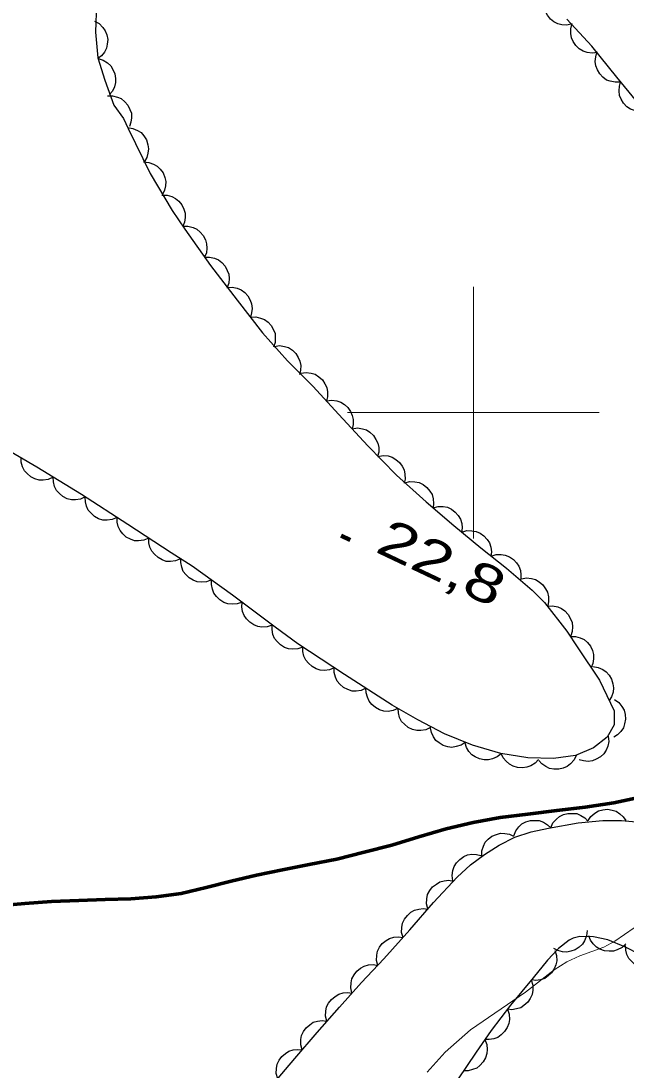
# Model space of a CAD drawing. Extents: x 356765 to 358572, y 5103174 to 5104650.
# Drawn here: x 357782.03 to 357806.07, y 5103573.84 to 5103615.55 of the extents above; entities that cross this region are included whole.
import ezdxf

# ---------------------------------------------------------------- set-up
doc = ezdxf.new("R2010")
doc.units = 0
doc.header["$LTSCALE"] = 0.6
doc.linetypes.add('DOT_DASHED', pattern=[7.7, 5, -1.2, 0.3, -1.2])
doc.linetypes.add('LONG_DASHED', pattern=[7.5, 6, -1.5])
for name, color, linetype, lineweight in [('2', 7, 'Continuous', 13), ('22', 7, 'Continuous', 35), ('3', 7, 'Continuous', 140), ('44', 7, 'Continuous', 25), ('61', 7, 'Continuous', 13)]:
    doc.layers.add(name, color=color, linetype=linetype, lineweight=lineweight)

msp = doc.modelspace()

# ---------------------------------------------------------------- linework, layer by layer
at = {"layer": '2'}
msp.add_lwpolyline([(357798.17, 5103573.8), (357798.88, 5103574.59), (357799.88, 5103575.48), (357802.07, 5103576.97), (357803.21, 5103577.86), (357803.72, 5103578.18), (357804.23, 5103578.42), (357805.19, 5103578.76), (357805.62, 5103579), (357806.77, 5103579.8)], dxfattribs=at)
at = {"layer": '22', "linetype": 'LONG_DASHED', "lineweight": 70}
msp.add_lwpolyline([(357781.12, 5103580.4), (357782.18, 5103580.5), (357783.24, 5103580.58), (357784.32, 5103580.62), (357785.37, 5103580.66), (357786.39, 5103580.69), (357787.4, 5103580.76), (357788.39, 5103580.9), (357789.38, 5103581.13), (357790.37, 5103581.38), (357791.38, 5103581.63), (357792.42, 5103581.84), (357793.48, 5103582.05), (357794.57, 5103582.26), (357795.66, 5103582.54), (357796.76, 5103582.82), (357797.83, 5103583.15), (357798.92, 5103583.46), (357799.99, 5103583.72), (357801.07, 5103583.92), (357802.17, 5103584.05), (357803.31, 5103584.19), (357804.44, 5103584.33), (357805.58, 5103584.5), (357806.7, 5103584.73)], dxfattribs=at)
at = {"layer": '3'}
msp.add_line((357794.75, 5103595.12), (357795.11, 5103594.95), dxfattribs=at)
at = {"layer": '44'}
for points in [[(357803.93, 5103615.44), (357803.72, 5103615.39), (357803.52, 5103615.4), (357803.36, 5103615.44), (357803.2, 5103615.52), (357803.06, 5103615.63), (357802.94, 5103615.79), (357802.86, 5103615.93), (357802.82, 5103616.1), (357802.8, 5103616.28), (357802.83, 5103616.46)], [(357784.95, 5103615.55), (357785.13, 5103615.45), (357785.28, 5103615.3), (357785.37, 5103615.17), (357785.43, 5103615.01), (357785.47, 5103614.82), (357785.45, 5103614.63), (357785.42, 5103614.47), (357785.34, 5103614.32), (357785.22, 5103614.17), (357785.08, 5103614.06)], [(357804.93, 5103614.31), (357804.72, 5103614.28), (357804.52, 5103614.31), (357804.36, 5103614.36), (357804.21, 5103614.45), (357804.07, 5103614.58), (357803.97, 5103614.74), (357803.9, 5103614.89), (357803.87, 5103615.06), (357803.87, 5103615.25), (357803.91, 5103615.42)], [(357785.09, 5103614.06), (357785.29, 5103614), (357785.46, 5103613.89), (357785.59, 5103613.78), (357785.68, 5103613.63), (357785.75, 5103613.46), (357785.78, 5103613.27), (357785.78, 5103613.11), (357785.74, 5103612.94), (357785.66, 5103612.77), (357785.54, 5103612.63)], [(357805.85, 5103613.13), (357805.64, 5103613.12), (357805.44, 5103613.16), (357805.29, 5103613.21), (357805.15, 5103613.32), (357805.02, 5103613.45), (357804.93, 5103613.62), (357804.86, 5103613.77), (357804.84, 5103613.94), (357804.86, 5103614.13), (357804.91, 5103614.3)], [(357806.8, 5103611.98), (357806.6, 5103611.96), (357806.4, 5103612), (357806.24, 5103612.05), (357806.1, 5103612.15), (357805.97, 5103612.29), (357805.87, 5103612.45), (357805.81, 5103612.6), (357805.79, 5103612.78), (357805.8, 5103612.96), (357805.85, 5103613.13)], [(357785.46, 5103612.58), (357785.66, 5103612.58), (357785.86, 5103612.53), (357786.01, 5103612.47), (357786.15, 5103612.35), (357786.27, 5103612.21), (357786.35, 5103612.04), (357786.41, 5103611.89), (357786.42, 5103611.71), (357786.39, 5103611.53), (357786.33, 5103611.36)], [(357786.26, 5103611.32), (357786.47, 5103611.29), (357786.66, 5103611.21), (357786.8, 5103611.12), (357786.91, 5103610.99), (357787.01, 5103610.83), (357787.06, 5103610.64), (357787.09, 5103610.48), (357787.07, 5103610.31), (357787.02, 5103610.13), (357786.93, 5103609.97)], [(357786.89, 5103609.96), (357787.1, 5103609.94), (357787.29, 5103609.87), (357787.44, 5103609.79), (357787.56, 5103609.67), (357787.67, 5103609.52), (357787.74, 5103609.34), (357787.78, 5103609.18), (357787.77, 5103609.01), (357787.73, 5103608.83), (357787.65, 5103608.66)], [(357787.62, 5103608.64), (357787.83, 5103608.64), (357788.02, 5103608.58), (357788.17, 5103608.51), (357788.3, 5103608.4), (357788.42, 5103608.25), (357788.5, 5103608.08), (357788.55, 5103607.92), (357788.55, 5103607.75), (357788.52, 5103607.57), (357788.46, 5103607.4)], [(357788.45, 5103607.4), (357788.66, 5103607.4), (357788.86, 5103607.35), (357789.01, 5103607.28), (357789.15, 5103607.17), (357789.27, 5103607.03), (357789.35, 5103606.86), (357789.4, 5103606.7), (357789.41, 5103606.53), (357789.39, 5103606.34), (357789.32, 5103606.17)], [(357789.31, 5103606.17), (357789.52, 5103606.18), (357789.72, 5103606.13), (357789.87, 5103606.07), (357790.01, 5103605.96), (357790.14, 5103605.82), (357790.22, 5103605.65), (357790.28, 5103605.5), (357790.3, 5103605.33), (357790.28, 5103605.14), (357790.22, 5103604.97)], [(357790.21, 5103604.97), (357790.42, 5103604.98), (357790.62, 5103604.94), (357790.77, 5103604.88), (357790.92, 5103604.77), (357791.04, 5103604.64), (357791.13, 5103604.47), (357791.19, 5103604.32), (357791.21, 5103604.14), (357791.19, 5103603.96), (357791.14, 5103603.79)], [(357791.14, 5103603.79), (357791.35, 5103603.8), (357791.54, 5103603.75), (357791.7, 5103603.7), (357791.84, 5103603.59), (357791.97, 5103603.46), (357792.06, 5103603.29), (357792.12, 5103603.14), (357792.13, 5103602.96), (357792.12, 5103602.78), (357792.06, 5103602.6)], [(357792.1, 5103602.63), (357792.3, 5103602.66), (357792.5, 5103602.62), (357792.66, 5103602.58), (357792.81, 5103602.48), (357792.94, 5103602.35), (357793.04, 5103602.19), (357793.11, 5103602.04), (357793.14, 5103601.87), (357793.13, 5103601.68), (357793.09, 5103601.51)], [(357793.15, 5103601.56), (357793.35, 5103601.59), (357793.56, 5103601.56), (357793.71, 5103601.52), (357793.86, 5103601.42), (357794, 5103601.3), (357794.1, 5103601.14), (357794.18, 5103600.99), (357794.21, 5103600.82), (357794.2, 5103600.63), (357794.16, 5103600.46)], [(357794.16, 5103600.46), (357794.37, 5103600.49), (357794.57, 5103600.46), (357794.73, 5103600.42), (357794.88, 5103600.32), (357795.01, 5103600.2), (357795.12, 5103600.04), (357795.19, 5103599.89), (357795.22, 5103599.72), (357795.22, 5103599.53), (357795.18, 5103599.36)], [(357795.18, 5103599.36), (357795.39, 5103599.39), (357795.59, 5103599.36), (357795.75, 5103599.31), (357795.89, 5103599.22), (357796.03, 5103599.09), (357796.13, 5103598.93), (357796.21, 5103598.79), (357796.24, 5103598.61), (357796.24, 5103598.43), (357796.19, 5103598.25)], [(357783.3, 5103597.43), (357783.11, 5103597.34), (357782.91, 5103597.32), (357782.75, 5103597.32), (357782.58, 5103597.37), (357782.41, 5103597.45), (357782.27, 5103597.58), (357782.16, 5103597.69), (357782.08, 5103597.85), (357782.03, 5103598.03), (357782.03, 5103598.21)], [(357796.21, 5103598.26), (357796.41, 5103598.3), (357796.61, 5103598.28), (357796.77, 5103598.23), (357796.92, 5103598.14), (357797.06, 5103598.02), (357797.17, 5103597.87), (357797.25, 5103597.72), (357797.28, 5103597.55), (357797.29, 5103597.36), (357797.25, 5103597.19)], [(357784.58, 5103596.65), (357784.39, 5103596.56), (357784.19, 5103596.53), (357784.03, 5103596.53), (357783.86, 5103596.58), (357783.69, 5103596.67), (357783.55, 5103596.79), (357783.44, 5103596.91), (357783.36, 5103597.07), (357783.31, 5103597.25), (357783.3, 5103597.43)], [(357797.28, 5103597.21), (357797.48, 5103597.26), (357797.68, 5103597.25), (357797.84, 5103597.22), (357798, 5103597.14), (357798.15, 5103597.03), (357798.27, 5103596.88), (357798.36, 5103596.75), (357798.4, 5103596.58), (357798.42, 5103596.39), (357798.4, 5103596.21)], [(357785.84, 5103595.83), (357785.65, 5103595.75), (357785.45, 5103595.72), (357785.28, 5103595.73), (357785.11, 5103595.78), (357784.95, 5103595.87), (357784.81, 5103596), (357784.7, 5103596.12), (357784.63, 5103596.28), (357784.59, 5103596.46), (357784.58, 5103596.64)], [(357798.4, 5103596.22), (357798.6, 5103596.27), (357798.8, 5103596.27), (357798.97, 5103596.24), (357799.13, 5103596.16), (357799.28, 5103596.05), (357799.4, 5103595.91), (357799.49, 5103595.77), (357799.54, 5103595.6), (357799.56, 5103595.42), (357799.53, 5103595.24)], [(357787.1, 5103595.01), (357786.91, 5103594.93), (357786.7, 5103594.91), (357786.54, 5103594.91), (357786.37, 5103594.97), (357786.21, 5103595.05), (357786.07, 5103595.18), (357785.96, 5103595.31), (357785.89, 5103595.47), (357785.85, 5103595.65), (357785.84, 5103595.83)], [(357799.54, 5103595.25), (357799.74, 5103595.31), (357799.94, 5103595.3), (357800.11, 5103595.28), (357800.27, 5103595.21), (357800.42, 5103595.1), (357800.55, 5103594.96), (357800.64, 5103594.82), (357800.69, 5103594.66), (357800.72, 5103594.47), (357800.7, 5103594.29)], [(357788.36, 5103594.19), (357788.16, 5103594.11), (357787.96, 5103594.09), (357787.8, 5103594.09), (357787.63, 5103594.15), (357787.47, 5103594.24), (357787.33, 5103594.37), (357787.22, 5103594.49), (357787.15, 5103594.65), (357787.1, 5103594.83), (357787.1, 5103595.01)], [(357800.71, 5103594.3), (357800.9, 5103594.36), (357801.11, 5103594.36), (357801.27, 5103594.34), (357801.43, 5103594.27), (357801.59, 5103594.17), (357801.72, 5103594.03), (357801.81, 5103593.9), (357801.87, 5103593.73), (357801.89, 5103593.55), (357801.88, 5103593.37)], [(357789.59, 5103593.35), (357789.4, 5103593.27), (357789.2, 5103593.26), (357789.03, 5103593.27), (357788.87, 5103593.34), (357788.71, 5103593.43), (357788.57, 5103593.57), (357788.47, 5103593.69), (357788.41, 5103593.86), (357788.37, 5103594.04), (357788.37, 5103594.22)], [(357790.82, 5103592.47), (357790.62, 5103592.4), (357790.42, 5103592.39), (357790.25, 5103592.4), (357790.09, 5103592.46), (357789.93, 5103592.56), (357789.79, 5103592.69), (357789.69, 5103592.82), (357789.63, 5103592.99), (357789.59, 5103593.17), (357789.59, 5103593.35)], [(357801.91, 5103593.39), (357802.11, 5103593.43), (357802.31, 5103593.41), (357802.47, 5103593.37), (357802.62, 5103593.28), (357802.76, 5103593.16), (357802.87, 5103593), (357802.95, 5103592.86), (357802.99, 5103592.68), (357802.99, 5103592.5), (357802.96, 5103592.32)], [(357792, 5103591.56), (357791.81, 5103591.49), (357791.6, 5103591.48), (357791.44, 5103591.5), (357791.28, 5103591.57), (357791.12, 5103591.67), (357790.99, 5103591.81), (357790.89, 5103591.94), (357790.83, 5103592.1), (357790.8, 5103592.28), (357790.81, 5103592.46)], [(357802.94, 5103592.31), (357803.15, 5103592.32), (357803.35, 5103592.28), (357803.5, 5103592.22), (357803.64, 5103592.12), (357803.77, 5103591.98), (357803.86, 5103591.81), (357803.92, 5103591.66), (357803.94, 5103591.49), (357803.92, 5103591.3), (357803.87, 5103591.13)], [(357793.22, 5103590.68), (357793.03, 5103590.61), (357792.82, 5103590.6), (357792.66, 5103590.61), (357792.49, 5103590.67), (357792.33, 5103590.77), (357792.2, 5103590.9), (357792.1, 5103591.03), (357792.03, 5103591.19), (357792, 5103591.38), (357792, 5103591.56)], [(357803.85, 5103591.11), (357804.06, 5103591.11), (357804.25, 5103591.05), (357804.4, 5103590.98), (357804.53, 5103590.87), (357804.65, 5103590.72), (357804.73, 5103590.55), (357804.78, 5103590.39), (357804.78, 5103590.22), (357804.75, 5103590.03), (357804.68, 5103589.87)], [(357794.47, 5103589.86), (357794.28, 5103589.78), (357794.08, 5103589.76), (357793.91, 5103589.77), (357793.75, 5103589.82), (357793.59, 5103589.91), (357793.45, 5103590.04), (357793.34, 5103590.17), (357793.27, 5103590.33), (357793.23, 5103590.51), (357793.23, 5103590.69)], [(357795.73, 5103589.05), (357795.54, 5103588.96), (357795.34, 5103588.94), (357795.18, 5103588.94), (357795.01, 5103589), (357794.84, 5103589.08), (357794.7, 5103589.21), (357794.59, 5103589.33), (357794.52, 5103589.49), (357794.47, 5103589.67), (357794.47, 5103589.85)], [(357804.75, 5103589.91), (357804.96, 5103589.88), (357805.14, 5103589.79), (357805.28, 5103589.7), (357805.39, 5103589.57), (357805.49, 5103589.41), (357805.54, 5103589.23), (357805.57, 5103589.06), (357805.55, 5103588.89), (357805.49, 5103588.71), (357805.4, 5103588.56)], [(357797, 5103588.24), (357796.81, 5103588.16), (357796.61, 5103588.13), (357796.44, 5103588.14), (357796.27, 5103588.19), (357796.11, 5103588.28), (357795.97, 5103588.4), (357795.86, 5103588.53), (357795.79, 5103588.69), (357795.74, 5103588.87), (357795.73, 5103589.05)], [(357805.61, 5103588.6), (357805.78, 5103588.48), (357805.9, 5103588.32), (357805.99, 5103588.18), (357806.03, 5103588.01), (357806.04, 5103587.82), (357806.01, 5103587.64), (357805.96, 5103587.48), (357805.86, 5103587.33), (357805.73, 5103587.2), (357805.58, 5103587.1)], [(357798.3, 5103587.49), (357798.11, 5103587.4), (357797.91, 5103587.37), (357797.75, 5103587.37), (357797.58, 5103587.41), (357797.41, 5103587.49), (357797.26, 5103587.62), (357797.15, 5103587.73), (357797.07, 5103587.89), (357797.02, 5103588.07), (357797.01, 5103588.25)], [(357799.68, 5103586.9), (357799.51, 5103586.79), (357799.31, 5103586.73), (357799.15, 5103586.7), (357798.98, 5103586.72), (357798.8, 5103586.78), (357798.64, 5103586.88), (357798.51, 5103586.98), (357798.41, 5103587.12), (357798.33, 5103587.29), (357798.29, 5103587.47)], [(357801.11, 5103586.45), (357800.95, 5103586.32), (357800.76, 5103586.24), (357800.6, 5103586.2), (357800.43, 5103586.2), (357800.25, 5103586.24), (357800.07, 5103586.32), (357799.94, 5103586.41), (357799.82, 5103586.54), (357799.73, 5103586.7), (357799.67, 5103586.87)], [(357805.36, 5103587.15), (357805.38, 5103586.94), (357805.34, 5103586.75), (357805.28, 5103586.59), (357805.18, 5103586.45), (357805.05, 5103586.32), (357804.88, 5103586.23), (357804.73, 5103586.16), (357804.56, 5103586.14), (357804.37, 5103586.16), (357804.2, 5103586.21)], [(357802.59, 5103586.22), (357802.45, 5103586.07), (357802.28, 5103585.97), (357802.12, 5103585.91), (357801.95, 5103585.89), (357801.76, 5103585.9), (357801.58, 5103585.96), (357801.43, 5103586.03), (357801.3, 5103586.15), (357801.19, 5103586.29), (357801.11, 5103586.46)], [(357804.09, 5103586.38), (357804, 5103586.2), (357803.86, 5103586.05), (357803.73, 5103585.94), (357803.57, 5103585.88), (357803.39, 5103585.84), (357803.2, 5103585.84), (357803.03, 5103585.86), (357802.88, 5103585.94), (357802.72, 5103586.05), (357802.6, 5103586.18)], [(357803.08, 5103583.51), (357803.16, 5103583.7), (357803.3, 5103583.85), (357803.42, 5103583.96), (357803.58, 5103584.03), (357803.76, 5103584.08), (357803.95, 5103584.08), (357804.11, 5103584.07), (357804.27, 5103584), (357804.43, 5103583.9), (357804.55, 5103583.77)], [(357804.56, 5103583.79), (357804.67, 5103583.96), (357804.83, 5103584.09), (357804.97, 5103584.18), (357805.14, 5103584.22), (357805.33, 5103584.24), (357805.51, 5103584.21), (357805.67, 5103584.16), (357805.82, 5103584.06), (357805.95, 5103583.94), (357806.06, 5103583.79)], [(357801.61, 5103583.19), (357801.69, 5103583.38), (357801.81, 5103583.54), (357801.93, 5103583.66), (357802.09, 5103583.74), (357802.27, 5103583.79), (357802.46, 5103583.8), (357802.62, 5103583.79), (357802.79, 5103583.73), (357802.95, 5103583.63), (357803.08, 5103583.51)], [(357800.33, 5103582.38), (357800.33, 5103582.59), (357800.4, 5103582.78), (357800.47, 5103582.93), (357800.59, 5103583.06), (357800.74, 5103583.17), (357800.92, 5103583.24), (357801.08, 5103583.29), (357801.25, 5103583.28), (357801.43, 5103583.25), (357801.6, 5103583.18)], [(357799.19, 5103581.4), (357799.16, 5103581.61), (357799.19, 5103581.81), (357799.24, 5103581.97), (357799.33, 5103582.12), (357799.46, 5103582.25), (357799.62, 5103582.36), (357799.77, 5103582.43), (357799.94, 5103582.46), (357800.13, 5103582.45), (357800.3, 5103582.41)], [(357798.19, 5103580.29), (357798.14, 5103580.49), (357798.15, 5103580.69), (357798.18, 5103580.85), (357798.27, 5103581.01), (357798.38, 5103581.16), (357798.53, 5103581.27), (357798.67, 5103581.36), (357798.84, 5103581.4), (357799.02, 5103581.42), (357799.2, 5103581.39)], [(357797.21, 5103579.15), (357797.15, 5103579.35), (357797.16, 5103579.55), (357797.19, 5103579.72), (357797.27, 5103579.87), (357797.38, 5103580.02), (357797.52, 5103580.15), (357797.66, 5103580.23), (357797.83, 5103580.28), (357798.01, 5103580.3), (357798.19, 5103580.28)], [(357804.52, 5103579.42), (357804.5, 5103579.21), (357804.42, 5103579.02), (357804.34, 5103578.88), (357804.21, 5103578.76), (357804.05, 5103578.66), (357803.87, 5103578.6), (357803.71, 5103578.57), (357803.54, 5103578.58), (357803.36, 5103578.63), (357803.2, 5103578.71)], [(357796.2, 5103578.04), (357796.15, 5103578.24), (357796.16, 5103578.44), (357796.19, 5103578.6), (357796.27, 5103578.76), (357796.38, 5103578.91), (357796.53, 5103579.03), (357796.67, 5103579.11), (357796.84, 5103579.16), (357797.03, 5103579.18), (357797.2, 5103579.15)], [(357806.06, 5103578.9), (357805.91, 5103578.75), (357805.72, 5103578.66), (357805.57, 5103578.61), (357805.39, 5103578.6), (357805.21, 5103578.62), (357805.03, 5103578.69), (357804.89, 5103578.77), (357804.76, 5103578.89), (357804.66, 5103579.04), (357804.59, 5103579.21)], [(357803.24, 5103578.63), (357803.3, 5103578.43), (357803.31, 5103578.22), (357803.28, 5103578.06), (357803.21, 5103577.9), (357803.11, 5103577.75), (357802.97, 5103577.62), (357802.84, 5103577.52), (357802.67, 5103577.47), (357802.48, 5103577.44), (357802.31, 5103577.46)], [(357807.32, 5103578.03), (357807.13, 5103577.95), (357806.93, 5103577.92), (357806.76, 5103577.92), (357806.59, 5103577.98), (357806.43, 5103578.06), (357806.29, 5103578.19), (357806.18, 5103578.31), (357806.1, 5103578.47), (357806.06, 5103578.65), (357806.05, 5103578.83)], [(357795.17, 5103576.95), (357795.13, 5103577.15), (357795.14, 5103577.35), (357795.17, 5103577.51), (357795.26, 5103577.67), (357795.37, 5103577.81), (357795.52, 5103577.93), (357795.66, 5103578.01), (357795.83, 5103578.06), (357796.02, 5103578.07), (357796.2, 5103578.04)], [(357802.3, 5103577.46), (357802.36, 5103577.26), (357802.36, 5103577.05), (357802.34, 5103576.89), (357802.26, 5103576.73), (357802.16, 5103576.58), (357802.01, 5103576.45), (357801.88, 5103576.36), (357801.71, 5103576.31), (357801.53, 5103576.28), (357801.35, 5103576.3)], [(357794.18, 5103575.82), (357794.13, 5103576.02), (357794.14, 5103576.22), (357794.17, 5103576.39), (357794.25, 5103576.54), (357794.36, 5103576.69), (357794.51, 5103576.81), (357794.65, 5103576.9), (357794.82, 5103576.95), (357795, 5103576.96), (357795.18, 5103576.94)], [(357801.35, 5103576.3), (357801.42, 5103576.1), (357801.43, 5103575.89), (357801.41, 5103575.73), (357801.34, 5103575.57), (357801.24, 5103575.41), (357801.1, 5103575.28), (357800.97, 5103575.18), (357800.81, 5103575.12), (357800.63, 5103575.09), (357800.45, 5103575.1)], [(357793.2, 5103574.68), (357793.14, 5103574.89), (357793.15, 5103575.09), (357793.17, 5103575.25), (357793.25, 5103575.41), (357793.36, 5103575.56), (357793.5, 5103575.68), (357793.64, 5103575.78), (357793.81, 5103575.83), (357793.99, 5103575.85), (357794.17, 5103575.83)], [(357800.45, 5103575.1), (357800.53, 5103574.9), (357800.55, 5103574.7), (357800.54, 5103574.54), (357800.48, 5103574.37), (357800.39, 5103574.21), (357800.26, 5103574.07), (357800.14, 5103573.96), (357799.97, 5103573.9), (357799.79, 5103573.85), (357799.61, 5103573.85)], [(357792.23, 5103573.54), (357792.17, 5103573.74), (357792.18, 5103573.95), (357792.2, 5103574.11), (357792.28, 5103574.27), (357792.39, 5103574.42), (357792.54, 5103574.54), (357792.67, 5103574.63), (357792.84, 5103574.68), (357793.02, 5103574.7), (357793.2, 5103574.68)]]:
    msp.add_lwpolyline(points, dxfattribs=at)
at = {"layer": '44', "linetype": 'DOT_DASHED'}
for points in [[(357785.02, 5103616.25), (357784.99, 5103615.11), (357785.08, 5103614.09), (357785.36, 5103613.21), (357785.72, 5103612.21), (357786.1, 5103611.68), (357786.28, 5103611.29), (357787.16, 5103609.5)], [(357806.8, 5103611.98), (357805.7, 5103613.32), (357804.71, 5103614.55), (357803.72, 5103615.63)], [(357787.16, 5103609.5), (357788.03, 5103608.03), (357788.53, 5103607.29), (357789.56, 5103605.84), (357790.61, 5103604.46), (357791.62, 5103603.17), (357792.61, 5103602.05), (357793.62, 5103601.05), (357794.66, 5103599.92), (357795.8, 5103598.68), (357796.94, 5103597.51), (357798.12, 5103596.46), (357799.22, 5103595.51), (357800.29, 5103594.63), (357801.31, 5103593.82), (357802.34, 5103592.95), (357802.82, 5103592.46), (357803.72, 5103591.32), (357804.15, 5103590.66), (357805.01, 5103589.37), (357805.6, 5103588.15), (357805.59, 5103587.59), (357805.31, 5103587.11), (357804.78, 5103586.68), (357804.06, 5103586.38), (357803.18, 5103586.26), (357802.17, 5103586.29), (357801.09, 5103586.46), (357799.96, 5103586.79), (357798.85, 5103587.24), (357797.79, 5103587.79), (357796.78, 5103588.38), (357794.88, 5103589.59), (357793.03, 5103590.82), (357792.12, 5103591.47), (357790.43, 5103592.75), (357788.82, 5103593.9), (357787.99, 5103594.43), (357786.27, 5103595.55), (357784.43, 5103596.74), (357782.65, 5103597.83), (357781.07, 5103598.76)], [(357792.02, 5103573.3), (357792.91, 5103574.34), (357793.79, 5103575.38), (357794.68, 5103576.38), (357795.56, 5103577.36), (357796.44, 5103578.3), (357797.47, 5103579.45), (357798.42, 5103580.54), (357799.35, 5103581.55), (357799.88, 5103582.03), (357800.44, 5103582.45), (357801.03, 5103582.82), (357801.65, 5103583.13), (357802.3, 5103583.34), (357802.98, 5103583.49), (357804.17, 5103583.7), (357805.15, 5103583.79), (357805.88, 5103583.79), (357806.62, 5103583.73)], [(357812.05, 5103573.78), (357810.96, 5103574.67), (357810.16, 5103575.38), (357809.2, 5103576.26), (357808.12, 5103577.25), (357807.05, 5103578.2), (357806.62, 5103578.47), (357806.04, 5103578.76), (357805.34, 5103579.05), (357804.78, 5103579.17), (357804.23, 5103579.19), (357803.96, 5103579.12), (357803.81, 5103579.04), (357803.38, 5103578.71), (357802.94, 5103578.25), (357802.38, 5103577.55), (357801.48, 5103576.46), (357800.71, 5103575.45), (357800.11, 5103574.59), (357799.37, 5103573.49)]]:
    msp.add_lwpolyline(points, dxfattribs=at)
at = {"layer": '61'}
for p, q in [((357800, 5103595), (357800, 5103605)), ((357795, 5103600), (357805, 5103600))]:
    msp.add_line(p, q, dxfattribs=at)

# ---------------------------------------------------------------- texts
at = {"layer": '3', "width": 1.35}
msp.add_text('22,8   ', height=1.5, rotation=334.619, dxfattribs=at).set_placement((357796.05, 5103594.49))

doc.saveas('drawing.dxf')
